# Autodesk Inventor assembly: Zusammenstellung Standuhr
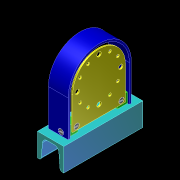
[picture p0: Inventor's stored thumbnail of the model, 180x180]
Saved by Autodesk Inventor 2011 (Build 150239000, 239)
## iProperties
Created: 2012-06
Part Number: Zusammenstellung Standuhr
Document SubType Name: Assembly
Designer: M.Schulte
Author: M.Schulte
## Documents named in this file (7)
- C:\Dokumente und Einstellungen\M.Schulte\Eigene Dateien\Matthias\Autodesk\Inventor\Inventor 2011\Schule\Standuhr 03.2011\Zusammenstellung Standuhr.iam
- C:\Dokumente und Einstellungen\M.Schulte\Eigene Dateien\Matthias\Autodesk\Inventor\Inventor 2011\Schule\Standuhr 03.2011\Fuß.ipt
- C:\Dokumente und Einstellungen\M.Schulte\Eigene Dateien\Matthias\Autodesk\Inventor\Inventor 2011\Schule\Standuhr 03.2011\Halterung.ipt
- C:\Dokumente und Einstellungen\M.Schulte\Eigene Dateien\Matthias\Autodesk\Inventor\Inventor 2011\Schule\Standuhr 03.2011\Zylinderkopfschraube-ISO 1207 - M4 x 12.ipt
- C:\Dokumente und Einstellungen\M.Schulte\Eigene Dateien\Matthias\Autodesk\Inventor\Inventor 2011\Schule\Standuhr 03.2011\Ziffernblatt.ipt
- C:\Dokumente und Einstellungen\M.Schulte\Eigene Dateien\Matthias\Autodesk\Inventor\Inventor 2011\Schule\Standuhr 03.2011\Senkkopfschraube-ISO 2009 - M4 x 12.ipt
- C:\Dokumente und Einstellungen\M.Schulte\Eigene Dateien\Matthias\Autodesk\Inventor\Inventor 2011\Schule\Standuhr 03.2011\Bügel.ipt
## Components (11 placed, 6 different names)
1. Fuß:1 — Passend:1, Passend:2, Passend:3, Passend:4, Winkel:1, Winkel:2, Einfügen:1, Einfügen:2, Passend:7, Passend:8
2. Halterung:1 — Passend:1, Passend:4, Winkel:1, Passend:5
3. Halterung:2 — Passend:2, Passend:3, Winkel:2, Passend:6, Passend:9
4. ISO 1207 M4 x 12:1 — Einfügen:1
5. ISO 1207 M4 x 12:2 — Einfügen:2
6. Ziffernblatt:1 — Passend:5, Passend:6, Einfügen:3, Einfügen:4, Fluchtend:1
7. ISO 2009 M4 x 12 x 7,9:1 — Einfügen:3
8. ISO 2009 M4 x 12 x 7,9:2 — Einfügen:4
9. Bügel:1 — Passend:7, Passend:8, Passend:9, Fluchtend:1, Einfügen:5, Einfügen:6
10. ISO 2009 M4 x 12 x 7,9:3 — Einfügen:6
11. ISO 2009 M4 x 12 x 7,9:4 — Einfügen:5
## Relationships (18: Mate 9, Insert 6, Angle 2, Flush 1)
- Passend:1 [Mate]: Fuß:1 ↔ Halterung:1
- Passend:2 [Mate]: Fuß:1 ↔ Halterung:2
- Passend:3 [Mate]: Fuß:1 ↔ Halterung:2
- Passend:4 [Mate]: Fuß:1 ↔ Halterung:1
- Winkel:1 [Angle]: Fuß:1 ↔ Halterung:1
- Winkel:2 [Angle]: Fuß:1 ↔ Halterung:2
- Einfügen:1 [Insert]: Fuß:1 ↔ ISO 1207 M4 x 12:1
- Einfügen:2 [Insert]: Fuß:1 ↔ ISO 1207 M4 x 12:2
- Passend:5 [Mate]: Halterung:1 ↔ Ziffernblatt:1
- Passend:6 [Mate]: Halterung:2 ↔ Ziffernblatt:1
- Einfügen:3 [Insert]: Ziffernblatt:1 ↔ ISO 2009 M4 x 12 x 7,9:1
- Einfügen:4 [Insert]: Ziffernblatt:1 ↔ ISO 2009 M4 x 12 x 7,9:2
- Passend:7 [Mate]: Fuß:1 ↔ Bügel:1
- Passend:8 [Mate]: Fuß:1 ↔ Bügel:1
- Passend:9 [Mate]: Halterung:2 ↔ Bügel:1
- Fluchtend:1 [Flush]: Ziffernblatt:1 ↔ Bügel:1
- Einfügen:5 [Insert]: Bügel:1 ↔ ISO 2009 M4 x 12 x 7,9:4
- Einfügen:6 [Insert]: Bügel:1 ↔ ISO 2009 M4 x 12 x 7,9:3
